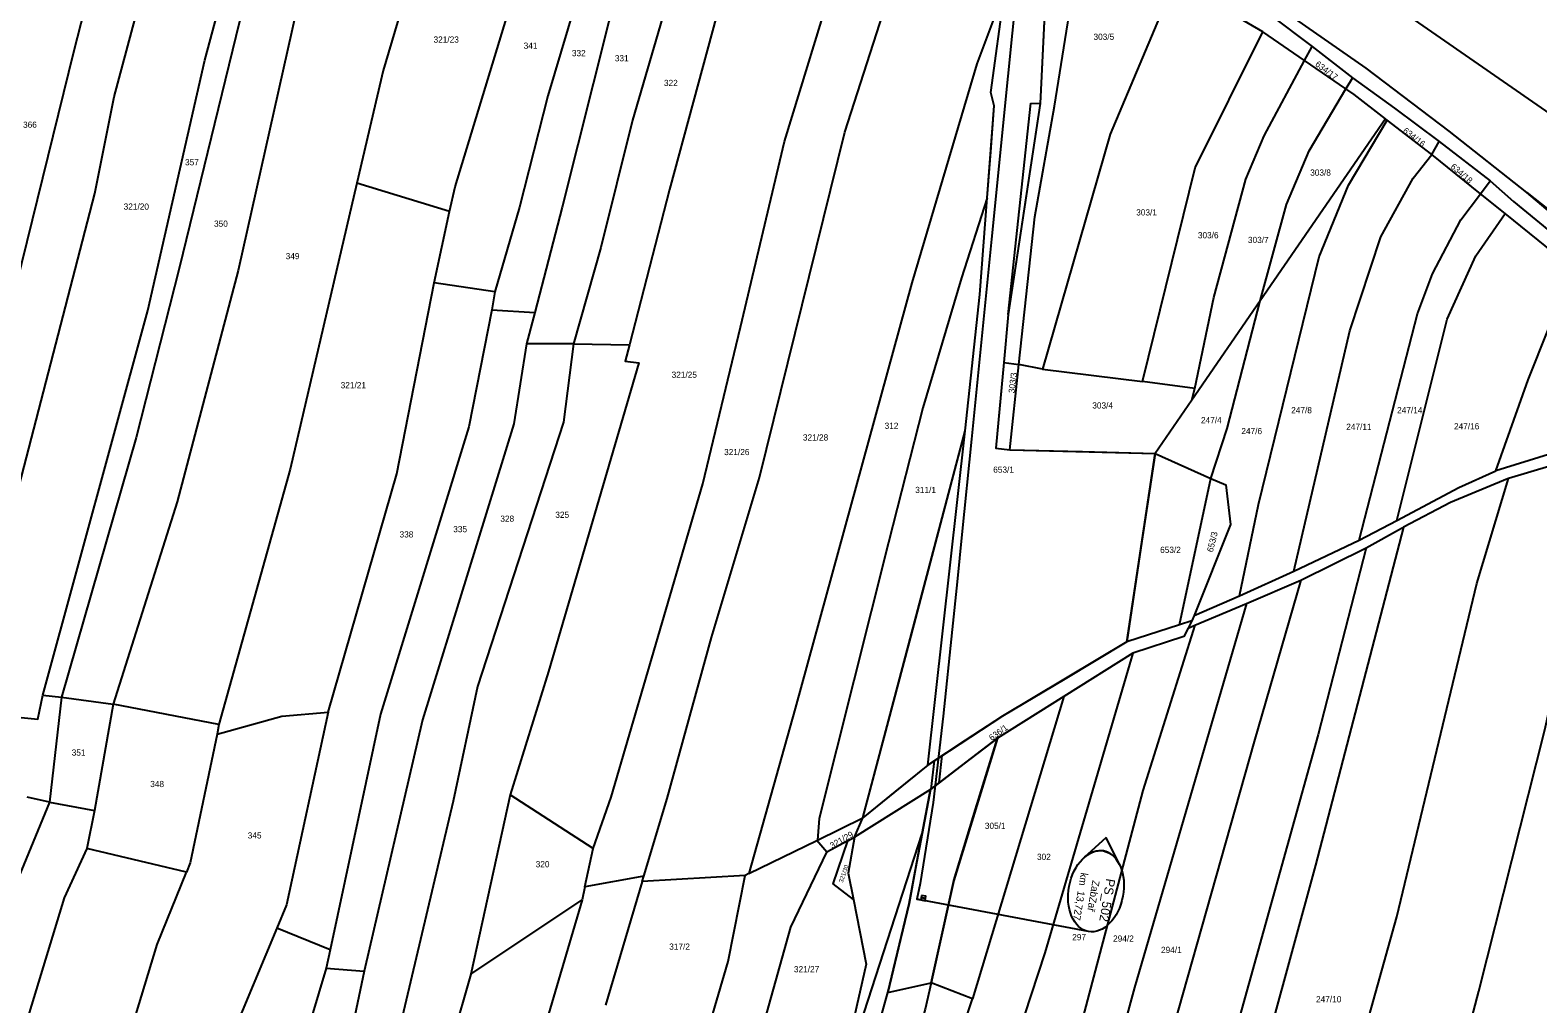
# Model space of a CAD drawing. Extents: x -746176 to -739709, y -1128407 to -1124482.
# Drawn here: x -743602.7 to -743188.7, y -1127823.5 to -1127556.1 of the extents above; entities that cross this region are included whole.
import ezdxf

# ---------------------------------------------------------------- set-up
doc = ezdxf.new("R2010")
doc.units = 0
for name, color, linetype in [('Vrstva 18', 7, 'Continuous'), ('Vrstva 21', 7, 'Continuous'), ('Vrstva 22', 7, 'Continuous'), ('Vrstva 32', 7, 'Continuous'), ('Vrstva 33', 7, 'Continuous'), ('Vrstva 34', 7, 'Continuous'), ('Vrstva 35', 7, 'Continuous'), ('Vrstva 42', 7, 'Continuous'), ('Vrstva 47', 7, 'Continuous'), ('Vrstva 5', 7, 'Continuous'), ('Vrstva 8', 7, 'Continuous')]:
    doc.layers.add(name, color=color, linetype=linetype)

msp = doc.modelspace()

# ---------------------------------------------------------------- linework, layer by layer
at = {"layer": 'Vrstva 18'}
msp.add_lwpolyline([(-743301.12, -1127329.13), (-743306.79, -1127349.51), (-743311.54, -1127370.06), (-743315.69, -1127392.87), (-743318.79, -1127415.84), (-743321.57, -1127442.6), (-743324.27, -1127469.35), (-743329.51, -1127521.46), (-743334.23, -1127568.82), (-743338.71, -1127613.56), (-743341.47, -1127641), (-743342.85, -1127654.73), (-743344.22, -1127668.45), (-743346.84, -1127694.61), (-743348.17, -1127707.68), (-743349.5, -1127720.75), (-743351.96, -1127744.53), (-743354.76, -1127768.22), (-743358.32, -1127790.48), (-743359.2, -1127794.79), (-743358.15, -1127794.97)], dxfattribs=at)
at = {"layer": 'Vrstva 21'}
for p, q in [((-743352.23, -1127755.36), (-743354.42, -1127756.79)), ((-743353.12, -1127762.84), (-743352.23, -1127755.36)), ((-743354.42, -1127756.79), (-743355.33, -1127764.53)), ((-743355.33, -1127764.53), (-743353.12, -1127762.84))]:
    msp.add_line(p, q, dxfattribs=at)
at = {"layer": 'Vrstva 22'}
for p, q in [((-743357.94, -1127793.74), (-743358.15, -1127794.97)), ((-743358.15, -1127794.97), (-743356.92, -1127795.19)), ((-743356.81, -1127794.57), (-743358.04, -1127794.36)), ((-743356.71, -1127793.96), (-743357.94, -1127793.74)), ((-743356.92, -1127795.19), (-743356.71, -1127793.96))]:
    msp.add_line(p, q, dxfattribs=at)
msp.add_lwpolyline([(-743357.94, -1127793.74), (-743358.04, -1127794.36), (-743356.81, -1127794.57), (-743356.71, -1127793.96), (-743357.94, -1127793.74)], dxfattribs=at)
at = {"layer": 'Vrstva 33'}
for p, q in [((-743264.18, -1127556.62), (-743288.35, -1127542.49)), ((-743252.73, -1127564.48), (-743264.18, -1127556.62)), ((-743252.73, -1127564.48), (-743250.66, -1127560.62)), ((-743250.66, -1127560.62), (-743239.62, -1127569.19)), ((-743241.42, -1127572.24), (-743252.73, -1127564.48)), ((-743239.62, -1127569.19), (-743241.42, -1127572.24)), ((-743230.52, -1127580.51), (-743264.95, -1127630.5)), ((-743230.04, -1127580.88), (-743230.52, -1127580.51)), ((-743217.78, -1127590.26), (-743230.04, -1127580.88)), ((-743217.78, -1127590.26), (-743215.78, -1127586.74)), ((-743204.41, -1127601.05), (-743217.78, -1127590.26)), ((-743215.78, -1127586.74), (-743201.77, -1127597.55)), ((-743487.51, -1127605.98), (-743512.98, -1127598.18)), ((-743204.41, -1127601.05), (-743201.77, -1127597.55)), ((-743197.68, -1127606.48), (-743204.41, -1127601.05)), ((-743491.75, -1127625.57), (-743487.51, -1127605.98)), ((-743475.06, -1127627.97), (-743491.75, -1127625.57)), ((-743475.06, -1127627.97), (-743475.93, -1127632.96)), ((-743264.95, -1127630.5), (-743283.69, -1127657.72)), ((-743475.93, -1127632.96), (-743464.14, -1127633.66)), ((-743464.14, -1127633.66), (-743466.39, -1127642.3)), ((-743453.46, -1127642.28), (-743466.39, -1127642.3)), ((-743453.46, -1127642.28), (-743438.1, -1127642.54)), ((-743335.37, -1127647.41), (-743331.17, -1127647.95)), ((-743333.67, -1127671.36), (-743331.17, -1127647.95)), ((-743324.73, -1127649.24), (-743331.17, -1127647.95)), ((-743324.73, -1127649.24), (-743297.22, -1127652.59)), ((-743282.86, -1127654.54), (-743297.22, -1127652.59)), ((-743283.69, -1127657.72), (-743282.86, -1127654.54)), ((-743283.69, -1127657.72), (-743293.8, -1127672.4)), ((-743333.67, -1127671.36), (-743293.8, -1127672.4)), ((-743301.55, -1127724.14), (-743293.8, -1127672.4)), ((-743293.8, -1127672.4), (-743278.45, -1127679.23)), ((-743165.44, -1127669.87), (-743196.8, -1127679.29)), ((-743287.1, -1127719.44), (-743278.45, -1127679.23)), ((-743237.76, -1127696.22), (-743227.38, -1127690.77)), ((-743255.66, -1127704.74), (-743237.76, -1127696.22)), ((-743253.81, -1127707.15), (-743235.82, -1127698.28)), ((-743270.64, -1127711.51), (-743255.66, -1127704.74)), ((-743268.66, -1127713.55), (-743253.81, -1127707.15)), ((-743283.11, -1127716.84), (-743270.64, -1127711.51)), ((-743282.88, -1127719.56), (-743268.66, -1127713.55)), ((-743283.71, -1127718.34), (-743287.1, -1127719.44)), ((-743283.71, -1127718.34), (-743284.74, -1127720.35)), ((-743283.11, -1127716.84), (-743283.71, -1127718.34)), ((-743287.1, -1127719.44), (-743301.55, -1127724.14)), ((-743284.74, -1127720.35), (-743282.88, -1127719.56)), ((-743299.93, -1127727.23), (-743318.89, -1127739.14)), ((-743599.16, -1127738.75), (-743594.04, -1127739.28)), ((-743594.04, -1127739.28), (-743597.33, -1127768.16)), ((-743594.04, -1127739.28), (-743579.85, -1127741.23)), ((-743318.89, -1127739.14), (-743343.93, -1127822.1)), ((-743318.89, -1127739.14), (-743337.1, -1127750.58)), ((-743579.85, -1127741.23), (-743585.04, -1127770.39)), ((-743550.89, -1127746.78), (-743579.85, -1127741.23)), ((-743550.89, -1127746.78), (-743551.29, -1127749.44)), ((-743355.5, -1127764.66), (-743337.1, -1127750.58)), ((-743597.33, -1127768.16), (-743603.54, -1127766.74)), ((-743597.33, -1127768.16), (-743585.04, -1127770.39)), ((-743470.88, -1127766.12), (-743481.69, -1127815.4)), ((-743448.1, -1127780.84), (-743470.88, -1127766.12)), ((-743355.5, -1127764.66), (-743376.33, -1127777.73)), ((-743357.75, -1127776.76), (-743355.5, -1127764.66)), ((-743585.04, -1127770.39), (-743587.1, -1127780.87)), ((-743386.45, -1127778.59), (-743374.07, -1127772.46)), ((-743376.33, -1127777.73), (-743374.07, -1127772.46)), ((-743405.3, -1127787.74), (-743386.64, -1127778.68)), ((-743386.64, -1127778.68), (-743386.45, -1127778.59)), ((-743383.94, -1127781.89), (-743386.64, -1127778.68)), ((-743378.18, -1127778.74), (-743383.94, -1127781.89)), ((-743378.18, -1127778.74), (-743376.33, -1127777.73)), ((-743559.77, -1127787.4), (-743587.1, -1127780.87)), ((-743450.34, -1127791.41), (-743448.1, -1127780.84)), ((-743434.17, -1127788.45), (-743450.34, -1127791.41)), ((-743406.34, -1127788.25), (-743434.62, -1127789.95)), ((-743434.62, -1127789.95), (-743434.17, -1127788.45)), ((-743405.3, -1127787.74), (-743406.34, -1127788.25)), ((-743450.34, -1127791.41), (-743451.09, -1127794.94)), ((-743434.62, -1127789.95), (-743444.74, -1127823.92)), ((-743481.69, -1127815.4), (-743451.09, -1127794.94)), ((-743520.33, -1127808.71), (-743534.94, -1127802.78)), ((-743520.33, -1127808.71), (-743521.42, -1127813.7)), ((-743521.42, -1127813.7), (-743511, -1127814.57)), ((-743511, -1127814.57), (-743513.93, -1127828.42)), ((-743481.69, -1127815.4), (-743490.01, -1127844.27)), ((-743343.93, -1127822.1), (-743355.31, -1127817.79)), ((-743351.87, -1127846.33), (-743343.93, -1127822.1))]:
    msp.add_line(p, q, dxfattribs=at)
for points in [[(-743551.54, -1127422.32), (-743561.28, -1127447), (-743590.72, -1127561.84), (-743612.33, -1127649.25), (-743636.86, -1127737.44)], [(-743621.23, -1127735.75), (-743612.44, -1127707.12), (-743584.91, -1127601.01), (-743579.58, -1127574.43), (-743546.31, -1127450.09), (-743538.8, -1127430.57)], [(-743599.16, -1127738.75), (-743570.37, -1127633.12), (-743554.73, -1127564.38), (-743526.58, -1127459.91), (-743519.14, -1127443.31)], [(-743514.57, -1127446.27), (-743521.89, -1127463.56), (-743545.21, -1127553.77), (-743561.74, -1127621.6), (-743573.61, -1127667.99), (-743594.04, -1127739.28)], [(-743498.56, -1127456.64), (-743508.94, -1127484.15), (-743529.52, -1127550.64), (-743545.56, -1127622.11), (-743562.33, -1127685.66), (-743579.85, -1127741.23)], [(-743474.35, -1127470.68), (-743486.04, -1127500.8), (-743505.77, -1127567.21), (-743512.98, -1127598.18)], [(-743487.51, -1127605.98), (-743486.02, -1127599.12), (-743462.28, -1127521.15), (-743455.14, -1127498.91), (-743448.36, -1127479.77)], [(-743431.85, -1127485.54), (-743442.53, -1127513.63), (-743460.53, -1127574.17), (-743468.34, -1127604.77), (-743475.06, -1127627.97)], [(-743421.29, -1127489.23), (-743434.5, -1127524.7), (-743443.83, -1127553.78), (-743456.63, -1127604.77), (-743464.14, -1127633.66)], [(-743409.64, -1127493.62), (-743419.11, -1127518.4), (-743437.32, -1127580.9), (-743446, -1127615.82), (-743453.46, -1127642.28)], [(-743394.17, -1127499.58), (-743406.86, -1127530.38), (-743414.11, -1127551.95), (-743427.12, -1127599.89), (-743438.1, -1127642.54)], [(-743448.1, -1127780.84), (-743443.18, -1127766.73), (-743418.02, -1127680.71), (-743407.6, -1127637.74), (-743395.56, -1127586.74), (-743381.16, -1127539.8), (-743369.67, -1127509.02)], [(-743434.17, -1127788.45), (-743427.78, -1127767.16), (-743415.63, -1127722.89), (-743402.41, -1127679.01), (-743378.99, -1127584.19), (-743364.14, -1127538.04), (-743355.14, -1127514.62)], [(-743314.91, -1127527.24), (-743320.68, -1127537.21), (-743321.34, -1127538.34), (-743323.67, -1127542.37), (-743325.37, -1127576.31), (-743334.16, -1127634.18), (-743335.37, -1127647.41)], [(-743314.71, -1127527.98), (-743288.02, -1127539.72), (-743267.92, -1127547.88), (-743262.15, -1127552), (-743250.66, -1127560.62)], [(-743331.17, -1127647.95), (-743326.84, -1127607.36), (-743321.41, -1127576.97), (-743314.01, -1127530.6)], [(-743110.84, -1127632.34), (-743140.32, -1127610.37), (-743254.82, -1127530.84)], [(-743288.35, -1127542.49), (-743306.14, -1127584.68), (-743324.73, -1127649.24)], [(-743339.88, -1127602.23), (-743337.94, -1127576.95), (-743338.86, -1127573.29), (-743335.16, -1127545.74)], [(-743191.76, -1127600.69), (-743213.04, -1127583.89), (-743235.8, -1127566.59), (-743259.6, -1127550), (-743265.25, -1127546.83)], [(-743337.56, -1127551.48), (-743342.72, -1127565.43), (-743360.58, -1127625.49), (-743392.64, -1127742.44), (-743405.3, -1127787.74)], [(-743297.22, -1127652.59), (-743282.79, -1127593.92), (-743264.18, -1127556.62)], [(-743282.86, -1127654.54), (-743277.65, -1127629.53), (-743268.85, -1127597.04), (-743263.84, -1127585.18), (-743252.73, -1127564.48)], [(-743239.62, -1127569.19), (-743228.08, -1127577.6), (-743215.78, -1127586.74)], [(-743264.95, -1127630.5), (-743257.74, -1127603.98), (-743251.48, -1127589.3), (-743241.42, -1127572.24)], [(-743230.52, -1127580.51), (-743239.1, -1127573.83), (-743241.42, -1127572.24)], [(-743270.64, -1127711.51), (-743265.43, -1127686.37), (-743248.78, -1127618.41), (-743240.66, -1127598.71), (-743230.04, -1127580.88)], [(-743255.66, -1127704.74), (-743240.36, -1127638.68), (-743231.77, -1127612.89), (-743222.92, -1127596.81), (-743217.78, -1127590.26)], [(-743512.98, -1127598.18), (-743531.28, -1127676.73), (-743550.89, -1127746.78)], [(-743201.77, -1127597.55), (-743195.41, -1127603.21), (-743175.98, -1127619.13)], [(-743339.88, -1127602.23), (-743346.97, -1127624.14), (-743357.58, -1127659.83), (-743366.95, -1127696.84), (-743386.06, -1127772.64), (-743386.45, -1127778.59)], [(-743374.07, -1127772.46), (-743345.92, -1127666.2), (-743341.91, -1127628.76), (-743339.88, -1127602.23)], [(-743237.76, -1127696.22), (-743221.74, -1127634), (-743217.66, -1127623.08), (-743209.85, -1127608.23), (-743204.41, -1127601.05)], [(-743119.31, -1127660.83), (-743131.7, -1127652.73), (-743150.41, -1127635.6), (-743191.76, -1127600.69)], [(-743191.76, -1127600.69), (-743179.42, -1127610.43), (-743144.82, -1127637.7), (-743125.82, -1127655.26)], [(-743227.38, -1127690.77), (-743213.64, -1127635.49), (-743205.71, -1127618.08), (-743197.68, -1127606.48)], [(-743177.68, -1127622.43), (-743184.29, -1127617.28), (-743197.68, -1127606.48)], [(-743200.21, -1127677.12), (-743191.34, -1127652.2), (-743185.76, -1127638.12), (-743177.68, -1127622.43)], [(-743520.82, -1127743.45), (-743502.02, -1127678), (-743491.75, -1127625.57)], [(-743278.45, -1127679.23), (-743274.02, -1127665.56), (-743264.95, -1127630.5)], [(-743475.93, -1127632.96), (-743482.22, -1127665.09), (-743506.51, -1127743.94), (-743520.33, -1127808.71)], [(-743466.39, -1127642.3), (-743469.86, -1127664.22), (-743494.95, -1127745.55), (-743511, -1127814.57)], [(-743453.46, -1127642.28), (-743456.19, -1127663.78), (-743479.83, -1127736.34), (-743486.56, -1127767.82), (-743500.98, -1127829.09)], [(-743438.1, -1127642.54), (-743439.27, -1127647.07), (-743435.59, -1127647.51), (-743460.31, -1127732.22), (-743470.88, -1127766.12)], [(-743335.37, -1127647.41), (-743337.51, -1127670.9), (-743333.67, -1127671.36)], [(-743170.99, -1127668.05), (-743171.32, -1127668.14), (-743200.21, -1127677.12)], [(-743237.87, -1127943.87), (-743228.87, -1127911.59), (-743204.89, -1127820), (-743186.75, -1127748.28), (-743176.72, -1127702.48), (-743165.44, -1127669.87)], [(-743227.38, -1127690.77), (-743210.43, -1127681.71), (-743200.21, -1127677.12)], [(-743278.45, -1127679.23), (-743274.37, -1127681.04), (-743273.1, -1127691.93), (-743283.11, -1127716.84)], [(-743264.74, -1127937.21), (-743244.37, -1127860.25), (-743227.42, -1127799.64), (-743205.44, -1127708.1), (-743196.8, -1127679.29)], [(-743196.8, -1127679.29), (-743197.04, -1127679.36), (-743212.68, -1127685.82), (-743225.59, -1127692.63)], [(-743225.59, -1127692.63), (-743249.75, -1127785.46), (-743287.33, -1127923.2), (-743297.04, -1127954.42)], [(-743235.82, -1127698.28), (-743226.1, -1127692.9), (-743225.59, -1127692.63)], [(-743235.82, -1127698.28), (-743249, -1127749.54), (-743300.05, -1127932.95), (-743303.92, -1127943.26)], [(-743253.81, -1127707.15), (-743266.62, -1127751.47), (-743299.27, -1127867.01), (-743314.24, -1127914.43)], [(-743268.66, -1127713.55), (-743299.42, -1127819.01), (-743313.64, -1127871.22), (-743325.19, -1127907.9)], [(-743282.88, -1127719.56), (-743297.14, -1127764.91), (-743314.44, -1127830.42), (-743327.83, -1127872.04)], [(-743284.74, -1127720.35), (-743285.9, -1127722.61), (-743299.93, -1127727.23)], [(-743301.55, -1127724.14), (-743335.67, -1127744.51), (-743356.23, -1127757.98), (-743374.07, -1127772.46)], [(-743299.93, -1127727.23), (-743324.05, -1127809.53), (-743337.26, -1127849.72)], [(-743623.51, -1127743.05), (-743600.59, -1127745.39), (-743599.16, -1127738.75)], [(-743551.29, -1127749.44), (-743533.58, -1127744.49), (-743520.82, -1127743.45)], [(-743520.82, -1127743.45), (-743532.26, -1127796.34), (-743534.94, -1127802.78)], [(-743551.29, -1127749.44), (-743558.72, -1127784.83), (-743559.77, -1127787.4)], [(-743337.1, -1127750.58), (-743349.06, -1127789.63), (-743355.31, -1127817.79)], [(-743597.33, -1127768.16), (-743606.36, -1127789.97), (-743626.72, -1127859.49), (-743638.35, -1127905.26), (-743659.84, -1127983.12)], [(-743388.31, -1127884.17), (-743374.7, -1127829.05), (-743357.75, -1127776.76)], [(-743388.31, -1127884.17), (-743381.41, -1127866.19), (-743374.06, -1127845.14), (-743367.18, -1127820.36), (-743361.33, -1127795.97), (-743357.75, -1127776.76)], [(-743376.61, -1127794.9), (-743382.22, -1127790.53), (-743378.18, -1127778.74)], [(-743376.33, -1127777.73), (-743378.06, -1127787.61), (-743376.61, -1127794.9)], [(-743587.1, -1127780.87), (-743593.35, -1127794.42), (-743608.73, -1127844.98), (-743637.18, -1127949.14), (-743646.98, -1127982.69)], [(-743440.39, -1127970.17), (-743422.4, -1127904.63), (-743393.77, -1127802.48), (-743383.94, -1127781.89)], [(-743573.69, -1127826.51), (-743567.83, -1127807.19), (-743559.77, -1127787.4)], [(-743416.75, -1127831.61), (-743411.02, -1127811.93), (-743406.34, -1127788.25)], [(-743451.09, -1127794.94), (-743476.79, -1127882.29), (-743506.61, -1128001.51)], [(-743376.61, -1127794.9), (-743373.1, -1127812.6), (-743383.25, -1127857.46), (-743405.64, -1127911.7), (-743425.47, -1127948.11), (-743440.39, -1127970.17)], [(-743534.94, -1127802.78), (-743547.45, -1127832.8), (-743549.4, -1127840.4)], [(-743521.42, -1127813.7), (-743536.99, -1127865.85), (-743543.84, -1127893.3), (-743572.96, -1128001.22)], [(-743355.31, -1127817.79), (-743356.91, -1127824.97), (-743366.89, -1127859.22), (-743379.33, -1127892.58), (-743393.74, -1127924.28), (-743408.65, -1127951.21)]]:
    msp.add_lwpolyline(points, dxfattribs=at)
at = {"layer": 'Vrstva 34'}
msp.add_line((-743312.1, -1127803.66), (-743359.2, -1127794.79), dxfattribs=at)
at = {"layer": 'Vrstva 35'}
for p, q in [((-743307.25, -1127777.86), (-743313.36, -1127783.41)), ((-743307.25, -1127777.86), (-743313.36, -1127783.41)), ((-743303.57, -1127785.25), (-743307.25, -1127777.86)), ((-743303.57, -1127785.25), (-743307.25, -1127777.86))]:
    msp.add_line(p, q, dxfattribs=at)
msp.add_ellipse((-743310.02, -1127792.6), major_axis=(-2.08, -11.06), ratio=0.666667, dxfattribs=at)
msp.add_ellipse((-743310.02, -1127792.6), major_axis=(2.08, 11.06), ratio=0.666473, start_param=5.557317, end_param=7.009053, dxfattribs=at)
at = {"layer": 'Vrstva 47'}
for p, q in [((-743334.16, -1127634.18), (-743327.93, -1127576.22)), ((-743327.93, -1127576.22), (-743325.37, -1127576.31)), ((-743356.23, -1127757.98), (-743345.92, -1127666.2))]:
    msp.add_line(p, q, dxfattribs=at)
at = {"layer": 'Vrstva 5'}
msp.add_lwpolyline([(-743323.67, -1127542.37), (-743324.52, -1127559.34), (-743325.37, -1127576.31), (-743329.77, -1127605.25), (-743334.16, -1127634.18), (-743335.37, -1127647.41), (-743336.44, -1127659.16), (-743337.51, -1127670.9), (-743333.67, -1127671.36), (-743313.73, -1127671.88), (-743293.8, -1127672.4), (-743297.68, -1127698.27), (-743301.55, -1127724.14), (-743318.61, -1127734.32), (-743335.67, -1127744.51), (-743345.95, -1127751.25), (-743356.23, -1127757.98), (-743365.15, -1127765.22), (-743374.07, -1127772.46), (-743359.99, -1127719.33), (-743345.92, -1127666.2), (-743341.91, -1127628.76), (-743339.88, -1127602.23), (-743338.91, -1127589.59), (-743337.94, -1127576.95), (-743338.86, -1127573.29), (-743335.16, -1127545.74)], dxfattribs=at)
msp.add_lwpolyline([(-743367.18, -1127820.36), (-743355.31, -1127817.79), (-743352.19, -1127803.71), (-743349.06, -1127789.63), (-743343.08, -1127770.1), (-743337.1, -1127750.58), (-743346.3, -1127757.62), (-743355.5, -1127764.66), (-743357.75, -1127776.76), (-743359.54, -1127786.36), (-743361.33, -1127795.97), (-743364.26, -1127808.17)], close=True, dxfattribs=at)
at = {"layer": 'Vrstva 8'}
msp.add_lwpolyline([(-743354.42, -1127756.79), (-743355.33, -1127764.53), (-743353.12, -1127762.84), (-743352.23, -1127755.36)], close=True, dxfattribs=at)

# ---------------------------------------------------------------- texts
at = {"layer": 'Vrstva 32'}
for s, height, p in [('km  13,727', 2, (-743314.18, -1127787.38)), ('ZabZař', 2, (-743310.98, -1127789.49)), ('PS_502', 2.5, (-743307.17, -1127789))]:
    msp.add_text(s, height=height, rotation=260.5528, dxfattribs=at).set_placement(p)
at = {"layer": 'Vrstva 42'}
for s, p in [('303/5', (-743310.71, -1127558.81)), ('321/23', (-743491.92, -1127559.57)), ('341', (-743467.17, -1127561.25)), ('332', (-743453.93, -1127563.29)), ('331', (-743442.14, -1127564.69)), ('322', (-743428.65, -1127571.49)), ('366', (-743604.63, -1127582.95)), ('357', (-743560.15, -1127593.26)), ('303/8', (-743251.21, -1127596.1)), ('321/20', (-743577.01, -1127605.44)), ('303/1', (-743298.98, -1127607.03)), ('350', (-743552.19, -1127610.13)), ('303/6', (-743282.05, -1127613.3)), ('303/7', (-743268.3, -1127614.6)), ('349', (-743532.52, -1127619.03)), ('321/25', (-743426.55, -1127651.61)), ('321/21', (-743517.42, -1127654.48)), ('303/4', (-743311.04, -1127660.04)), ('247/8', (-743256.43, -1127661.34)), ('247/14', (-743227.34, -1127661.34)), ('312', (-743368.06, -1127665.63)), ('247/4', (-743281.19, -1127664.08)), ('247/11', (-743241.31, -1127665.91)), ('247/16', (-743211.72, -1127665.77)), ('321/28', (-743390.5, -1127668.83)), ('247/6', (-743270.11, -1127667.08)), ('321/26', (-743412.13, -1127672.84)), ('653/1', (-743338.24, -1127677.68)), ('311/1', (-743359.65, -1127683.25)), ('328', (-743473.57, -1127691.14)), ('325', (-743458.48, -1127690.06)), ('338', (-743501.25, -1127695.45)), ('335', (-743486.51, -1127694.01)), ('653/2', (-743292.41, -1127699.7)), ('351', (-743591.27, -1127755.37)), ('348', (-743569.71, -1127764)), ('345', (-743542.94, -1127778.11)), ('305/1', (-743340.54, -1127775.48)), ('320', (-743463.87, -1127786.02)), ('302', (-743326.22, -1127783.99)), ('297', (-743316.55, -1127806.06)), ('294/2', (-743305.33, -1127806.45)), ('317/2', (-743427.21, -1127808.66)), ('294/1', (-743292.17, -1127809.55)), ('321/27', (-743392.96, -1127814.86)), ('247/10', (-743249.61, -1127823.1))]:
    msp.add_text(s, height=1.7, dxfattribs=at).set_placement(p)
for s, height, rotation, p in [('634/17', 1.7, 323, (-743249.99, -1127565.8)), ('634/16', 1.7, 322, (-743225.92, -1127584.07)), ('634/18', 1.7, 319, (-743212.8, -1127593.85)), ('303/3', 1.7, 83, (-743332.39, -1127655.92)), ('653/3', 1.7, 76, (-743277.95, -1127699.61)), ('636/1', 1.7, 36, (-743338.64, -1127751.38)), ('321/29', 1.7, 30, (-743382.47, -1127780.96)), ('321/30', 1.19, 71, (-743379.55, -1127790.35))]:
    msp.add_text(s, height=height, rotation=rotation, dxfattribs=at).set_placement(p)

doc.saveas('drawing.dxf')
